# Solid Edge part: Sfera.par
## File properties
Title: Sfera Ø 39 cm
Author: DESYS
Template: Normal.par
Last saved by: Luca
Revision: 6
Application: Solid Edge
Tipo di contenuto documento: 0
Precisione: 0,990
Document Number: 8009
Revision: 0
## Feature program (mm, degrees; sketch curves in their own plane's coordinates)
lofted protrusion "unnamed LoftedProtrusion 1"
lofted cutout "unnamed LoftedCutout 1"
sketch for "unnamed Protrusion 1" plane through (0, 0, -140) normal (0, 0, -1) x-axis (1, 0, 0)
  circle centre (0, 0) radius 90
extrude "unnamed Protrusion 1" add finite 10 along +normal
fillet "Rotondo_1" radius 10
sketch for "Foro_1" plane through (0, 0, -150) normal (0, 0, -1) x-axis (1, 0, 0)
  hole centre (0, 0) bore radius 25
hole "Foro_1" diameter 50 through
sketch for "Foro_2" plane through (0, 0, -150) normal (0, 0, -1) x-axis (1, 0, 0)
  hole centre (0, -75) bore radius 5
hole "Foro_2" diameter 10 finite
sketch for "unnamed Hole 1" plane through (0, 0, -150) normal (0, 0, -1) x-axis (1, 0, 0)
  hole centre (0, 75) bore radius 5
hole "unnamed Hole 1" finite
sketch for "Foro_4" plane through (0, 0, -150) normal (0, 0, -1) x-axis (1, 0, 0)
  hole centre (-75, 0) bore radius 5
hole "Foro_4" diameter 10 finite
sketch for "unnamed Hole 2" plane through (0, 0, -150) normal (0, 0, -1) x-axis (1, 0, 0)
  hole centre (75, 0) bore radius 5
hole "unnamed Hole 2" finite
sketch for "Foro_6" plane through (0, 0, -150) normal (0, 0, -1) x-axis (1, 0, 0)
  hole centre (0, 75) bore radius 7
hole "Foro_6" diameter 14 finite
sketch for "unnamed Hole 3" plane through (0, 0, -150) normal (0, 0, -1) x-axis (1, 0, 0)
  hole centre (0, -75) bore radius 7
hole "unnamed Hole 3" finite
sketch for "ExtrudedCutout_1" #1 plane through (0, 0, -150) normal (0, 0, -1) x-axis (1, 0, 0)
  circle centre (0, 0) radius 35
sketch for "ExtrudedCutout_1" #2 plane through (0, 0, -150) normal (0, 0, -1) x-axis (1, 0, 0)
  arc centre (8.3783, -57.3917) radius 7 from (5.3707, -63.7126) to (9.3895, -64.3182) ccw
  arc centre (8.3783, 57.3917) radius 7 from (9.3895, 64.3182) to (5.3707, 63.7126) ccw
  arc centre (-8.3783, 57.3917) radius 7 from (-5.3707, 63.7126) to (-9.3895, 64.3182) ccw
  arc centre (0, 0) radius 65 from (-9.3895, -64.3182) to (-9.3895, 64.3182) cw
  arc centre (-8.3783, -57.3917) radius 7 from (-9.3895, -64.3182) to (-5.3707, -63.7126) ccw
extrude "ExtrudedCutout_1" cut finite 10 along -normal
draft "Draft_1"  Angles1 = 50 deg
fillet "Rotondo_2" radius 7
fillet "Rotondo_3" radius 6
fillet "Rotondo_4" radius 5
fillet "Rotondo_5" radius 5
fillet "Rotondo_6" radius 7
fillet "Rotondo_7" radius 10
pattern "unnamed Pattern 1" of "Foro_2", "unnamed Hole 1"
pattern "unnamed Pattern 2" of "Foro_4", "unnamed Hole 2"
pattern "unnamed Pattern 3" of "Foro_6", "unnamed Hole 3"
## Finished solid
Body 1: solid body, 46 faces, 73 edges, 28 vertices.
  Faces by surface: torus 18, plane 10, cone 8, cylinder 7, blend 2, spline 1
  Edges by curve: circle 53, intersection 12, line 8
Bounding box of the edges (mm; curved faces can reach further): 395.967 x 395.967 x 150.000, from (-197.9833, -197.9833, -150) to (197.9833, 197.9833, 0).
Cylindrical faces by radius (mm): R5 x4, R7 x2, R25 x1
Conical faces (half-angle, radius in mm at the cone's reference point): 50 deg R7 x4, 50 deg R12.5 x2, 50 deg R65 x2
Toroidal faces (ring radius, tube radius in mm): R4.1744 r200 x1, R9.1838 r6 x4, R10.3162 r6 x2, R26.9653 r7 x2, R30 r5 x1, R40 r5 x1, R50.5347 r7 x2, R67.1838 r6 x2, R85.0492 r5 x1, R100 r10 x1, R191.2 r7 x1
Planar faces by outward normal: +z 1, -z 9
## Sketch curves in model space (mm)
arc centre (-10.5656, 0, 44.4203) radius 180 from (-184.9985, 0, 0) through (-122.5274, 0, -96.5213) to (-25, 0, -135)
circle centre (0, 0, -135) radius 25
circle centre (0, 0, 0) radius 185
arc centre (-4.1744, 0, 40.6487) radius 200 from (-200, 0, 0) through (-161.438, 0, -82.9156) to (-90, 0, -140)
circle centre (0, 0, -140) radius 90
circle centre (0, 0, 0) radius 200
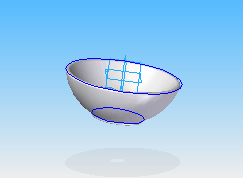
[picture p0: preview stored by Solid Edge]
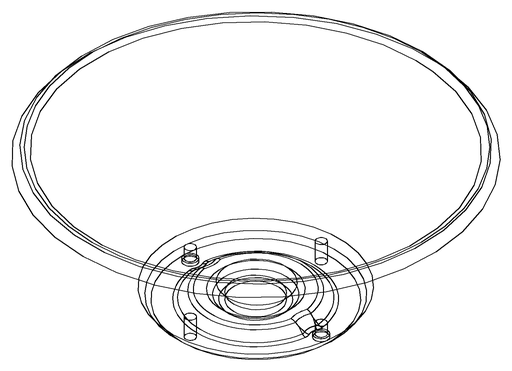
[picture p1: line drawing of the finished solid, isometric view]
